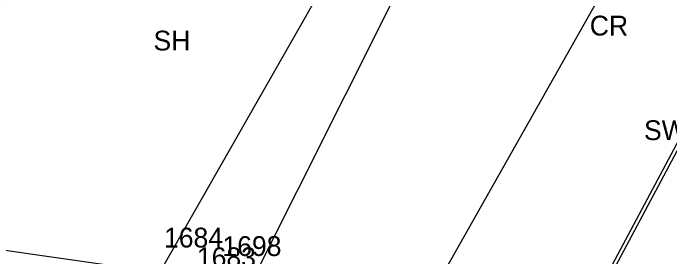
# Model space of a CAD drawing. Extents: x 462930 to 463548, y 29607 to 30453.
# Drawn here: x 463342.46 to 463362.64, y 30154.04 to 30161.54 of the extents above; entities that cross this region are included whole.
import ezdxf

# ---------------------------------------------------------------- set-up
doc = ezdxf.new("R2010")
doc.units = 0
for name, color, linetype in [('DCP', 7, 'Continuous'), ('L_A', 7, 'Continuous'), ('L_I', 7, 'Continuous'), ('LELB', 7, 'Continuous'), ('P_A', 7, 'Continuous'), ('PET', 7, 'Continuous'), ('PRC', 7, 'Continuous'), ('R_A', 7, 'Continuous'), ('R_I', 7, 'Continuous'), ('RC', 7, 'Continuous'), ('RDG', 7, 'Continuous')]:
    doc.layers.add(name, color=color, linetype=linetype)

msp = doc.modelspace()

# ---------------------------------------------------------------- linework, layer by layer
at = {"layer": 'DCP'}
msp.add_lwpolyline([(463354.963, 30167.616), (463343.04, 30146.69)], dxfattribs=at)
at = {"layer": 'LELB'}
msp.add_lwpolyline([(463355.606, 30164.89), (463349.727, 30153.154)], dxfattribs=at)
at = {"layer": 'PET'}
msp.add_lwpolyline([(463357.128, 30146.779), (463364.23, 30160.089), (463372.211, 30170.687), (463380.439, 30181.089), (463388.986, 30192.495), (463395.438, 30204.072), (463399.65, 30216.413), (463402.389, 30229.411), (463403.525, 30242.02), (463404.007, 30246.74), (463403.926, 30248.538), (463404.123, 30251.434)], dxfattribs=at)
at = {"layer": 'PRC'}
msp.add_lwpolyline([(463399.789, 30246.987), (463397.991, 30230.027), (463395.304, 30217.172), (463391.095, 30206.312), (463384.492, 30195.113), (463376.573, 30184.227), (463367.848, 30173.371), (463360.659, 30162.372), (463353.283, 30149.309)], dxfattribs=at)
at = {"layer": 'RC'}
msp.add_lwpolyline([(463403.888, 30243.164), (463403.731, 30243.164), (463403.598, 30241.759), (463402.492, 30229.375), (463399.74, 30216.359), (463395.506, 30204.018), (463389.016, 30192.435), (463380.487, 30181.016), (463372.297, 30170.609), (463364.316, 30160.034), (463357.246, 30146.767)], dxfattribs=at)
at = {"layer": 'RDG'}
msp.add_lwpolyline([(463347.931, 30153.415), (463337.62, 30154.896), (463328.703, 30158.04), (463317.438, 30162.728), (463318.8, 30166.246), (463327.27, 30162.794), (463340.451, 30158.117), (463344.729, 30166.901), (463353.138, 30164.992), (463357.576, 30167.469)], dxfattribs=at)

# ---------------------------------------------------------------- texts
at = {"layer": 'L_A'}
msp.add_text('SH', height=0.6096, dxfattribs=at).set_placement((463346.773, 30160.388))
at = {"layer": 'L_I'}
msp.add_text('1698', height=0.6096, dxfattribs=at).set_placement((463348.892, 30154.068))
at = {"layer": 'P_A'}
msp.add_text('CR', height=0.6096, dxfattribs=at).set_placement((463360.181, 30160.848))
at = {"layer": 'R_A'}
msp.add_text('SWP ST JT 1882', height=0.6096, dxfattribs=at).set_placement((463361.847, 30157.632))
at = {"layer": 'R_I'}
for s, p in [('1684', (463347.096, 30154.329)), ('1684', (463347.096, 30154.329)), ('1683', (463348.107, 30153.723))]:
    msp.add_text(s, height=0.6096, dxfattribs=at).set_placement(p)

doc.saveas('drawing.dxf')
